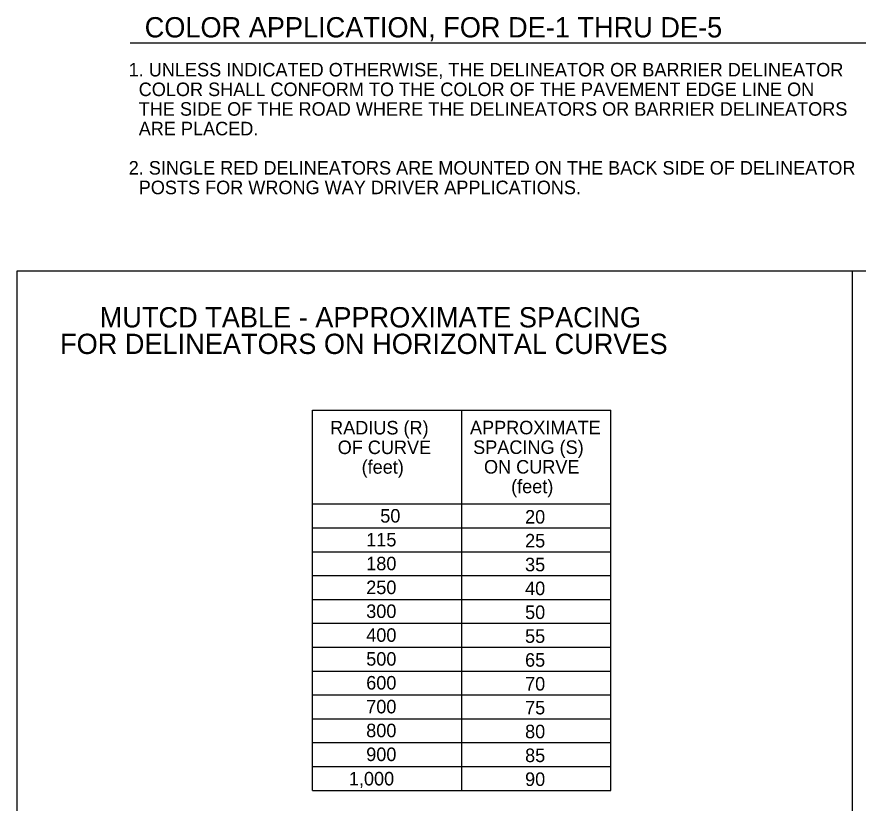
# Model space of a CAD drawing. Extents: x -0.14 to 2.7, y -0.05 to 1.78.
# Drawn here: x 1.222 to 1.74, y 0.237 to 0.721 of the extents above; entities that cross this region are included whole.
import ezdxf

# ---------------------------------------------------------------- set-up
doc = ezdxf.new("R2010")
doc.units = 0
doc.layers.add('CT_CSHT_GeneralLabel', color=7, linetype='Continuous')

msp = doc.modelspace()

# ---------------------------------------------------------------- linework, layer by layer
at = {"layer": 'CT_CSHT_GeneralLabel'}
for p, q in [((1.29182, 0.7053), (1.76009, 0.7053)), ((1.22199, 0.56476), (1.22199, 0.08)), ((2.64583, 0.56476), (1.22199, 0.56476)), ((1.73657, 0.56476), (1.73657, 0.08)), ((1.40413, 0.47929), (1.58788, 0.47929)), ((1.40413, 0.24505), (1.40413, 0.47929)), ((1.49601, 0.24505), (1.49601, 0.47929)), ((1.58788, 0.24505), (1.58788, 0.47929)), ((1.40413, 0.42143), (1.58788, 0.42143)), ((1.40413, 0.40673), (1.58788, 0.40673)), ((1.40413, 0.39203), (1.58788, 0.39203)), ((1.40413, 0.37733), (1.58788, 0.37733)), ((1.40413, 0.36263), (1.58788, 0.36263)), ((1.40413, 0.34793), (1.58788, 0.34793)), ((1.40413, 0.33323), (1.58788, 0.33323)), ((1.40413, 0.31853), (1.58788, 0.31853)), ((1.40413, 0.30383), (1.58788, 0.30383)), ((1.40413, 0.28913), (1.58788, 0.28913)), ((1.40413, 0.27443), (1.58788, 0.27443)), ((1.40413, 0.25973), (1.58788, 0.25973)), ((1.40413, 0.24505), (1.58788, 0.24505))]:
    msp.add_line(p, q, dxfattribs=at)

# ---------------------------------------------------------------- texts
for s, height, p in [('COLOR APPLICATION, FOR DE-1 THRU DE-5', 0.0125, (1.30075, 0.70873)), ('1. UNLESS INDICATED OTHERWISE, THE DELINEATOR OR BARRIER DELINEATOR ', 0.0083333, (1.29089, 0.68469)), ('  COLOR SHALL CONFORM TO THE COLOR OF THE PAVEMENT EDGE LINE ON', 0.0083333, (1.29089, 0.6726)), ('  THE SIDE OF THE ROAD WHERE THE DELINEATORS OR BARRIER DELINEATORS', 0.0083333, (1.29089, 0.66052)), ('  ARE PLACED.', 0.0083333, (1.29089, 0.64844)), ('2. SINGLE RED DELINEATORS ARE MOUNTED ON THE BACK SIDE OF DELINEATOR', 0.0083333, (1.29089, 0.62427)), ('  POSTS FOR WRONG WAY DRIVER APPLICATIONS.', 0.0083333, (1.29089, 0.61219)), ('MUTCD TABLE - APPROXIMATE SPACING', 0.0125, (1.27304, 0.53014)), ('FOR DELINEATORS ON HORIZONTAL CURVES', 0.0125, (1.24861, 0.51378)), ('RADIUS (R)', 0.008333, (1.41497, 0.46423)), ('APPROXIMATE', 0.0083333, (1.50112, 0.46431)), ('OF CURVE', 0.008333, (1.41963, 0.45215)), ('SPACING (S)', 0.0083333, (1.50307, 0.45223)), ('(feet)', 0.008333, (1.43437, 0.44006)), ('ON CURVE', 0.008333, (1.50976, 0.44014)), ('(feet) ', 0.008333, (1.52647, 0.42806)), ('50', 0.008333, (1.44586, 0.40996)), ('20', 0.008333, (1.53506, 0.40933)), ('115', 0.008333, (1.43721, 0.39528)), ('25', 0.008333, (1.53506, 0.39465)), ('180', 0.008333, (1.43721, 0.38059)), ('35', 0.008333, (1.53506, 0.37996)), ('250', 0.008333, (1.43721, 0.3659)), ('40', 0.008333, (1.53506, 0.36527)), ('300', 0.008333, (1.43721, 0.35121)), ('50', 0.008333, (1.53506, 0.35058)), ('400', 0.008333, (1.43721, 0.33653)), ('55', 0.008333, (1.53506, 0.3359)), ('500', 0.008333, (1.43721, 0.32184)), ('65', 0.008333, (1.53506, 0.32121)), ('600', 0.008333, (1.43721, 0.30715)), ('70', 0.008333, (1.53506, 0.30652)), ('700', 0.008333, (1.43721, 0.29246)), ('75', 0.008333, (1.53506, 0.29183)), ('800', 0.008333, (1.43721, 0.27778)), ('80', 0.008333, (1.53506, 0.27715)), ('900', 0.008333, (1.43721, 0.26309)), ('85', 0.008333, (1.53506, 0.26246)), ('1,000', 0.008333, (1.42652, 0.24809)), ('90', 0.008333, (1.53506, 0.24777))]:
    msp.add_text(s, height=height, dxfattribs=at).set_placement(p)

doc.saveas('drawing.dxf')
